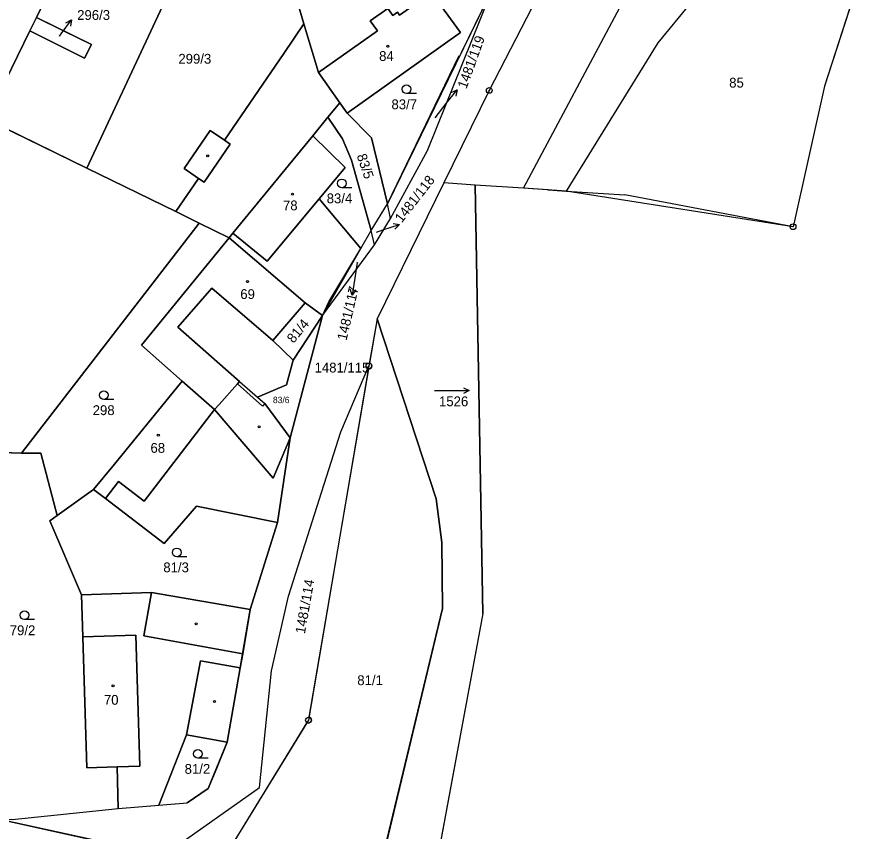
# Model space of a CAD drawing. Extents: x -760642 to -757221, y -1092371 to -1088855.
# Drawn here: x -758933.7 to -758787.7, y -1089822.5 to -1089681.5 of the extents above; entities that cross this region are included whole.
import ezdxf

# ---------------------------------------------------------------- set-up
doc = ezdxf.new("R2010")
doc.units = 0
for name, color, linetype in [('Vrstva 1', 7, 'Continuous'), ('Vrstva 13', 7, 'Continuous'), ('Vrstva 16', 7, 'Continuous'), ('Vrstva 18', 7, 'Continuous'), ('Vrstva 19', 7, 'Continuous'), ('Vrstva 24', 7, 'Continuous'), ('Vrstva 25', 7, 'Continuous'), ('Vrstva 26', 7, 'Continuous'), ('Vrstva 27', 7, 'Continuous'), ('Vrstva 28', 7, 'Continuous'), ('Vrstva 4', 7, 'Continuous')]:
    doc.layers.add(name, color=color, linetype=linetype)

msp = doc.modelspace()

# ---------------------------------------------------------------- linework, layer by layer
at = {"layer": 'Vrstva 1'}
for p, q in [((-758897.45, -1089655.89), (-758921.61, -1089707.71)), ((-758836.23, -1089663.58), (-758851.99, -1089694.25)), ((-758846.04, -1089711.19), (-758823.54, -1089668.77)), ((-758926.27, -1089673.32), (-758930.34, -1089681.62)), ((-758851.17, -1089676.07), (-758869.61, -1089713.9)), ((-758862.67, -1089704.66), (-758851.17, -1089676.07)), ((-758885.64, -1089677.33), (-758884.05, -1089682.7)), ((-758862.01, -1089677.31), (-758856.94, -1089684.25)), ((-758817.26, -1089679.2), (-758822.82, -1089686.02)), ((-758930.34, -1089681.62), (-758931.48, -1089683.95)), ((-758920.83, -1089686.29), (-758930.34, -1089681.62)), ((-758884.05, -1089682.7), (-758887.55, -1089687.84)), ((-758884.05, -1089682.7), (-758881.54, -1089691.15)), ((-758931.48, -1089683.95), (-758938.98, -1089699.23)), ((-758931.48, -1089683.95), (-758921.99, -1089688.64)), ((-758856.94, -1089684.25), (-758876.57, -1089698.16)), ((-758921.99, -1089688.64), (-758920.83, -1089686.29)), ((-758822.82, -1089686.02), (-758838.67, -1089711.68)), ((-758887.55, -1089687.84), (-758897.79, -1089702.88)), ((-758877.84, -1089696.37), (-758881.54, -1089691.15)), ((-758851.99, -1089694.25), (-758859.85, -1089710.27)), ((-758879.9, -1089698.89), (-758877.84, -1089696.37)), ((-758877.84, -1089696.37), (-758876.57, -1089698.16)), ((-758938.98, -1089699.23), (-758921.61, -1089707.71)), ((-758882.53, -1089702.1), (-758879.9, -1089698.89)), ((-758879.9, -1089698.89), (-758877.37, -1089702.61)), ((-758876.57, -1089698.16), (-758872.38, -1089702.46)), ((-758904.75, -1089707.78), (-758900.27, -1089701.19)), ((-758900.27, -1089701.19), (-758897.79, -1089702.88)), ((-758882.53, -1089702.1), (-758876.9, -1089707.61)), ((-758877.37, -1089702.61), (-758875.81, -1089706.3)), ((-758872.38, -1089702.46), (-758869.61, -1089713.9)), ((-758869.09, -1089716.42), (-758862.67, -1089704.66)), ((-758875.81, -1089706.3), (-758872.44, -1089718.5)), ((-758921.61, -1089707.71), (-758906.21, -1089715.23)), ((-758902.28, -1089709.47), (-758904.75, -1089707.78)), ((-758881.43, -1089713.02), (-758876.9, -1089707.61)), ((-758902.28, -1089709.47), (-758906.21, -1089715.23)), ((-758859.85, -1089710.27), (-758871.39, -1089733.79)), ((-758854.44, -1089710.64), (-758859.85, -1089710.27)), ((-758881.43, -1089713.02), (-758874.22, -1089721.62)), ((-758872.44, -1089718.5), (-758869.61, -1089713.9)), ((-758869.09, -1089716.42), (-758869.61, -1089713.9)), ((-758906.21, -1089715.23), (-758902.17, -1089717.2)), ((-758871.85, -1089720.98), (-758869.09, -1089716.42)), ((-758902.17, -1089717.2), (-758932.89, -1089757.04)), ((-758902.17, -1089717.2), (-758896.96, -1089719.75)), ((-758902.41, -1089726.41), (-758896.96, -1089719.75)), ((-758896.96, -1089719.75), (-758883.85, -1089731)), ((-758874.22, -1089721.62), (-758872.44, -1089718.5)), ((-758871.85, -1089720.98), (-758872.44, -1089718.5)), ((-758880.83, -1089733.19), (-758871.85, -1089720.98)), ((-758879.72, -1089730.85), (-758874.22, -1089721.62)), ((-758908.04, -1089733.3), (-758902.41, -1089726.41)), ((-758889.45, -1089737.53), (-758883.85, -1089731)), ((-758883.85, -1089731), (-758880.83, -1089733.19)), ((-758880.83, -1089733.19), (-758879.72, -1089730.85)), ((-758912.16, -1089738.33), (-758908.04, -1089733.3)), ((-758880.83, -1089733.19), (-758886.42, -1089754.39)), ((-758885.92, -1089740.95), (-758880.83, -1089733.19)), ((-758871.39, -1089733.79), (-758872.81, -1089741.94)), ((-758871.39, -1089733.79), (-758861.15, -1089764.91)), ((-758912.16, -1089738.33), (-758905.1, -1089744.55)), ((-758889.45, -1089737.53), (-758885.92, -1089740.95)), ((-758885.92, -1089740.95), (-758887.05, -1089745.23)), ((-758872.81, -1089741.94), (-758883.26, -1089803.24)), ((-758877.68, -1089753.34), (-758872.81, -1089741.94)), ((-758905.1, -1089744.55), (-758905.42, -1089744.94)), ((-758905.1, -1089744.55), (-758899.5, -1089749.48)), ((-758916.84, -1089758.91), (-758905.42, -1089744.94)), ((-758895.56, -1089745.01), (-758898.7, -1089748.58)), ((-758895.56, -1089745.01), (-758891.2, -1089748.87)), ((-758892.11, -1089747.33), (-758887.05, -1089745.23)), ((-758892.11, -1089747.33), (-758890.83, -1089748.45)), ((-758898.7, -1089748.58), (-758899.5, -1089749.48)), ((-758890.83, -1089748.45), (-758891.2, -1089748.87)), ((-758886.42, -1089754.39), (-758890.83, -1089748.45)), ((-758886.71, -1089781.78), (-758877.68, -1089753.34)), ((-758886.42, -1089754.39), (-758888.61, -1089769.01)), ((-758932.89, -1089757.04), (-758946.76, -1089756.58)), ((-758932.89, -1089757.04), (-758929.58, -1089757.04)), ((-758929.58, -1089757.04), (-758926.72, -1089767.81)), ((-758920.43, -1089763.32), (-758916.84, -1089758.91)), ((-758926.72, -1089767.81), (-758920.43, -1089763.32)), ((-758920.43, -1089763.32), (-758918.39, -1089764.88)), ((-758918.39, -1089764.88), (-758908.22, -1089772.65)), ((-758861.15, -1089764.91), (-758860.19, -1089772.49)), ((-758902.61, -1089766.19), (-758908.22, -1089772.65)), ((-758888.61, -1089769.01), (-758902.61, -1089766.19)), ((-758928, -1089768.73), (-758926.72, -1089767.81)), ((-758928, -1089768.73), (-758922.54, -1089781.57)), ((-758888.61, -1089769.01), (-758893.33, -1089784.09)), ((-758860.19, -1089772.49), (-758860.09, -1089783.94)), ((-758910.43, -1089781.16), (-758922.54, -1089781.57)), ((-758910.43, -1089781.16), (-758893.33, -1089784.09)), ((-758922.32, -1089788.8), (-758922.54, -1089781.57)), ((-758889.66, -1089794.72), (-758886.71, -1089781.78)), ((-758893.33, -1089784.09), (-758894.65, -1089791.79)), ((-758860.09, -1089783.94), (-758872.24, -1089834.59)), ((-758921.62, -1089811.49), (-758922.32, -1089788.8)), ((-758894.65, -1089791.79), (-758895.06, -1089794.17)), ((-758895.06, -1089794.17), (-758897.32, -1089807.05)), ((-758891.72, -1089814.9), (-758889.66, -1089794.72)), ((-758883.26, -1089803.24), (-758896.92, -1089825.49)), ((-758904.37, -1089805.81), (-758909.15, -1089817.97)), ((-758904.37, -1089805.81), (-758897.32, -1089807.05)), ((-758897.32, -1089807.05), (-758899.14, -1089811.48)), ((-758916.38, -1089811.33), (-758921.62, -1089811.49)), ((-758916.38, -1089811.33), (-758916.21, -1089818.53)), ((-758899.14, -1089811.48), (-758900.63, -1089815.1)), ((-758908.4, -1089826.64), (-758891.72, -1089814.9)), ((-758900.63, -1089815.1), (-758904.26, -1089817.58)), ((-758909.15, -1089817.97), (-758904.26, -1089817.58)), ((-758934.53, -1089820.44), (-758916.21, -1089818.53)), ((-758916.21, -1089818.53), (-758909.15, -1089817.97)), ((-758937.97, -1089820.13), (-758908.4, -1089826.64))]:
    msp.add_line(p, q, dxfattribs=at)
at = {"layer": 'Vrstva 13'}
for p, q in [((-758787.66, -1089673.88), (-758793.98, -1089693.51)), ((-758793.98, -1089693.51), (-758799.44, -1089717.83)), ((-758846.04, -1089711.19), (-758854.44, -1089710.64)), ((-758853.09, -1089784.76), (-758854.44, -1089710.64)), ((-758841.79, -1089711.47), (-758846.04, -1089711.19)), ((-758841.79, -1089711.47), (-758838.67, -1089711.68)), ((-758838.67, -1089711.68), (-758828.55, -1089712.34)), ((-758799.44, -1089717.83), (-758828.55, -1089712.34)), ((-758853.09, -1089784.76), (-758862.96, -1089838.01))]:
    msp.add_line(p, q, dxfattribs=at)
at = {"layer": 'Vrstva 16'}
for p, q in [((-758926.04, -1089684.47), (-758924.276, -1089682.043)), ((-758926.33, -1089684.86), (-758926.04, -1089684.47)), ((-758859.42, -1089696.51), (-758857.571, -1089694.147)), ((-758861.35, -1089698.98), (-758859.42, -1089696.51)), ((-758871.51, -1089718.77), (-758870.38, -1089718.4)), ((-758870.38, -1089718.4), (-758867.53, -1089717.462)), ((-758874.84, -1089724.04), (-758875.25, -1089726.73)), ((-758875.25, -1089726.73), (-758875.701, -1089729.696))]:
    msp.add_line(p, q, dxfattribs=at)
for points in [[(-758925.268, -1089682.558), (-758924.276, -1089682.043), (-758924.46, -1089683.146)], [(-758858.581, -1089694.627), (-758857.571, -1089694.147), (-758857.794, -1089695.243)], [(-758868.637, -1089717.3), (-758867.53, -1089717.462), (-758868.324, -1089718.25)], [(-758875.056, -1089728.782), (-758875.701, -1089729.696), (-758876.045, -1089728.632)]]:
    msp.add_lwpolyline(points, dxfattribs=at)
at = {"layer": 'Vrstva 24'}
for centre, radius in [((-758851.99, -1089694.25), 0.5), ((-758851.99, -1089694.25), 0.0327), ((-758799.44, -1089717.83), 0.5), ((-758799.44, -1089717.83), 0.0327), ((-758872.81, -1089741.94), 0.5), ((-758872.81, -1089741.94), 0.0327), ((-758883.26, -1089803.24), 0.5), ((-758883.26, -1089803.24), 0.0327)]:
    msp.add_circle(centre, radius, dxfattribs=at)
at = {"layer": 'Vrstva 25'}
for p, q in [((-758864.57, -1089694.8), (-758866.32, -1089694.8)), ((-758875.74, -1089711.08), (-758877.49, -1089711.08)), ((-758861.45, -1089746.21), (-758855.45, -1089746.21)), ((-758916.93, -1089747.74), (-758918.68, -1089747.74)), ((-758904.31, -1089774.95), (-758906.06, -1089774.95)), ((-758930.64, -1089785.84), (-758932.39, -1089785.84)), ((-758900.64, -1089809.83), (-758902.39, -1089809.83))]:
    msp.add_line(p, q, dxfattribs=at)
msp.add_lwpolyline([(-758856.45, -1089745.71), (-758855.45, -1089746.21), (-758856.45, -1089746.71)], dxfattribs=at)
for centre, radius in [((-758869.54, -1089686.61), 0.175), ((-758866.32, -1089694.05), 0.75), ((-758900.7, -1089705.58), 0.175), ((-758877.49, -1089710.33), 0.75), ((-758886.03, -1089712.22), 0.175), ((-758893.83, -1089727.34), 0.175), ((-758918.68, -1089746.99), 0.75), ((-758891.79, -1089752.49), 0.175), ((-758909.24, -1089753.9), 0.175), ((-758906.06, -1089774.2), 0.75), ((-758932.39, -1089785.09), 0.75), ((-758902.7, -1089786.58), 0.175), ((-758917.08, -1089797.31), 0.175), ((-758899.53, -1089800.02), 0.175), ((-758902.39, -1089809.08), 0.75)]:
    msp.add_circle(centre, radius, dxfattribs=at)
at = {"layer": 'Vrstva 26'}
for points in [[(-758916.3, -1089625.5), (-758949.19, -1089694.25), (-758938.98, -1089699.23), (-758931.48, -1089683.95), (-758930.34, -1089681.62), (-758926.27, -1089673.32), (-758913.77, -1089627.67), (-758916.3, -1089625.5)], [(-758925.644, -1089683.926), (-758920.83, -1089686.29), (-758921.99, -1089688.64), (-758931.48, -1089683.95), (-758938.98, -1089699.23), (-758921.61, -1089707.71), (-758897.45, -1089655.89), (-758894.2, -1089649.19), (-758897.14, -1089645.53), (-758899.45, -1089641.9), (-758901.79, -1089638.23), (-758902.79, -1089636.72), (-758904.5, -1089640.06), (-758913.77, -1089627.67), (-758926.27, -1089673.32), (-758930.34, -1089681.62), (-758925.644, -1089683.926)], [(-758887.39, -1089670.98), (-758890.72, -1089658.51), (-758892.71, -1089653.18), (-758894.2, -1089649.19), (-758897.45, -1089655.89), (-758921.61, -1089707.71), (-758906.21, -1089715.23), (-758902.28, -1089709.47), (-758904.75, -1089707.78), (-758900.27, -1089701.19), (-758897.79, -1089702.88), (-758887.55, -1089687.84), (-758884.05, -1089682.7), (-758885.64, -1089677.33), (-758887.39, -1089670.98)], [(-758881.54, -1089691.15), (-758871.34, -1089683.92), (-758872.57, -1089682.19), (-758869.54, -1089680.04), (-758868.66, -1089681.29), (-758867.86, -1089680.72), (-758867.51, -1089681.21), (-758862.01, -1089677.31), (-758860.46, -1089676.21), (-758853.08, -1089674.92), (-758853.39, -1089667.08), (-758877.98, -1089668.72), (-758876.34, -1089674.39), (-758885.64, -1089677.33), (-758884.05, -1089682.7), (-758881.54, -1089691.15)], [(-758876.57, -1089698.16), (-758872.38, -1089702.46), (-758869.61, -1089713.9), (-758851.17, -1089676.07), (-758853.08, -1089674.92), (-758860.46, -1089676.21), (-758862.01, -1089677.31), (-758856.94, -1089684.25), (-758876.57, -1089698.16)], [(-758867.51, -1089681.21), (-758867.86, -1089680.72), (-758868.66, -1089681.29), (-758869.54, -1089680.04), (-758872.57, -1089682.19), (-758871.34, -1089683.92), (-758881.54, -1089691.15), (-758877.84, -1089696.37), (-758876.57, -1089698.16), (-758856.94, -1089684.25), (-758862.01, -1089677.31), (-758867.51, -1089681.21)], [(-758925.644, -1089683.926), (-758930.34, -1089681.62), (-758931.48, -1089683.95), (-758921.99, -1089688.64), (-758920.83, -1089686.29), (-758925.644, -1089683.926)], [(-758896.96, -1089719.75), (-758896.33, -1089718.98), (-758882.53, -1089702.1), (-758879.9, -1089698.89), (-758877.84, -1089696.37), (-758881.54, -1089691.15), (-758884.05, -1089682.7), (-758887.55, -1089687.84), (-758897.79, -1089702.88), (-758896.81, -1089703.55), (-758901.29, -1089710.14), (-758902.28, -1089709.47), (-758906.21, -1089715.23), (-758902.17, -1089717.2), (-758896.96, -1089719.75)], [(-758906.21, -1089715.23), (-758921.61, -1089707.71), (-758938.98, -1089699.23), (-758949.19, -1089694.25), (-758964.56, -1089686.74), (-758974.54, -1089701.27), (-758971.37, -1089702.86), (-758990.85, -1089743.47), (-758977.57, -1089750.63), (-758963.52, -1089755.7), (-758946.76, -1089756.58), (-758932.89, -1089757.04), (-758902.17, -1089717.2), (-758906.21, -1089715.23)], [(-758879.9, -1089698.89), (-758877.37, -1089702.61), (-758875.81, -1089706.3), (-758872.44, -1089718.5), (-758869.61, -1089713.9), (-758872.38, -1089702.46), (-758876.57, -1089698.16), (-758877.84, -1089696.37), (-758879.9, -1089698.89)], [(-758882.53, -1089702.1), (-758876.9, -1089707.61), (-758881.43, -1089713.02), (-758874.22, -1089721.62), (-758872.44, -1089718.5), (-758875.81, -1089706.3), (-758877.37, -1089702.61), (-758879.9, -1089698.89), (-758882.53, -1089702.1)], [(-758902.28, -1089709.47), (-758901.29, -1089710.14), (-758896.81, -1089703.55), (-758897.79, -1089702.88), (-758900.27, -1089701.19), (-758904.75, -1089707.78), (-758902.28, -1089709.47)], [(-758890.44, -1089723.79), (-758881.43, -1089713.02), (-758876.9, -1089707.61), (-758882.53, -1089702.1), (-758896.33, -1089718.98), (-758890.44, -1089723.79)], [(-758881.43, -1089713.02), (-758890.44, -1089723.79), (-758896.33, -1089718.98), (-758896.96, -1089719.75), (-758883.85, -1089731), (-758880.83, -1089733.19), (-758879.72, -1089730.85), (-758874.22, -1089721.62), (-758881.43, -1089713.02)], [(-758902.17, -1089717.2), (-758932.89, -1089757.04), (-758929.58, -1089757.04), (-758926.72, -1089767.81), (-758920.43, -1089763.32), (-758916.84, -1089758.91), (-758905.42, -1089744.94), (-758905.1, -1089744.55), (-758912.16, -1089738.33), (-758908.04, -1089733.3), (-758902.41, -1089726.41), (-758896.96, -1089719.75), (-758902.17, -1089717.2)], [(-758899.5, -1089749.48), (-758898.7, -1089748.58), (-758895.56, -1089745.01), (-758895.2, -1089744.6), (-758905.86, -1089735.22), (-758900, -1089728.48), (-758889.45, -1089737.53), (-758883.85, -1089731), (-758896.96, -1089719.75), (-758902.41, -1089726.41), (-758908.04, -1089733.3), (-758912.16, -1089738.33), (-758905.1, -1089744.55), (-758899.5, -1089749.48)], [(-758889.45, -1089737.53), (-758900, -1089728.48), (-758905.86, -1089735.22), (-758895.2, -1089744.6), (-758892.11, -1089747.33), (-758887.05, -1089745.23), (-758885.92, -1089740.95), (-758889.45, -1089737.53)], [(-758889.45, -1089737.53), (-758885.92, -1089740.95), (-758880.83, -1089733.19), (-758883.85, -1089731), (-758889.45, -1089737.53)], [(-758896.451, -1089825.663), (-758872.24, -1089834.59), (-758860.09, -1089783.94), (-758860.19, -1089772.49), (-758861.15, -1089764.91), (-758871.39, -1089733.79), (-758872.724, -1089741.447)], [(-758896.451, -1089825.663), (-758872.24, -1089834.59), (-758860.09, -1089783.94), (-758860.19, -1089772.49), (-758861.15, -1089764.91), (-758871.39, -1089733.79), (-758872.724, -1089741.447)], [(-758885.92, -1089740.95), (-758887.05, -1089745.23), (-758892.11, -1089747.33), (-758890.83, -1089748.45), (-758886.42, -1089754.39), (-758880.83, -1089733.19), (-758885.92, -1089740.95)], [(-758872.894, -1089742.433), (-758883.176, -1089802.747)], [(-758872.894, -1089742.433), (-758883.176, -1089802.747)], [(-758916.14, -1089761.95), (-758911.7, -1089765.36), (-758899.5, -1089749.48), (-758905.1, -1089744.55), (-758905.42, -1089744.94), (-758916.84, -1089758.91), (-758920.43, -1089763.32), (-758918.39, -1089764.88), (-758916.14, -1089761.95)], [(-758889.4, -1089761.34), (-758886.42, -1089754.39), (-758890.83, -1089748.45), (-758891.2, -1089748.87), (-758895.56, -1089745.01), (-758898.7, -1089748.58), (-758899.5, -1089749.48), (-758889.4, -1089761.34)], [(-758911.7, -1089765.36), (-758916.14, -1089761.95), (-758918.39, -1089764.88), (-758908.22, -1089772.65), (-758902.61, -1089766.19), (-758888.61, -1089769.01), (-758886.42, -1089754.39), (-758889.4, -1089761.34), (-758899.5, -1089749.48), (-758911.7, -1089765.36)], [(-758946.46, -1089758.4), (-758943.42, -1089780.49), (-758937.97, -1089820.13), (-758934.53, -1089820.44), (-758916.21, -1089818.53), (-758916.38, -1089811.33), (-758921.62, -1089811.49), (-758922.32, -1089788.8), (-758922.54, -1089781.57), (-758928, -1089768.73), (-758926.72, -1089767.81), (-758929.58, -1089757.04), (-758932.89, -1089757.04), (-758946.76, -1089756.58), (-758946.46, -1089758.4)], [(-758926.72, -1089767.81), (-758928, -1089768.73), (-758922.54, -1089781.57), (-758910.43, -1089781.16), (-758893.33, -1089784.09), (-758888.61, -1089769.01), (-758902.61, -1089766.19), (-758908.22, -1089772.65), (-758918.39, -1089764.88), (-758920.43, -1089763.32), (-758926.72, -1089767.81)], [(-758922.32, -1089788.8), (-758913.14, -1089788.52), (-758912.44, -1089811.21), (-758916.38, -1089811.33), (-758916.21, -1089818.53), (-758909.15, -1089817.97), (-758904.37, -1089805.81), (-758901.96, -1089792.95), (-758895.06, -1089794.17), (-758894.65, -1089791.79), (-758911.72, -1089788.65), (-758910.43, -1089781.16), (-758922.54, -1089781.57), (-758922.32, -1089788.8)], [(-758910.43, -1089781.16), (-758911.72, -1089788.65), (-758894.65, -1089791.79), (-758893.33, -1089784.09), (-758910.43, -1089781.16)], [(-758916.38, -1089811.33), (-758912.44, -1089811.21), (-758913.14, -1089788.52), (-758922.32, -1089788.8), (-758921.62, -1089811.49), (-758916.38, -1089811.33)], [(-758895.06, -1089794.17), (-758901.96, -1089792.95), (-758904.37, -1089805.81), (-758897.32, -1089807.05), (-758895.06, -1089794.17)], [(-758883.522, -1089803.666), (-758896.658, -1089825.064)], [(-758883.522, -1089803.666), (-758896.658, -1089825.064)], [(-758897.32, -1089807.05), (-758904.37, -1089805.81), (-758909.15, -1089817.97), (-758904.26, -1089817.58), (-758900.63, -1089815.1), (-758899.14, -1089811.48), (-758897.32, -1089807.05)], [(-758977.118, -1089818.836), (-758981.19, -1089818.61), (-758994.11, -1089817.55), (-758994.67, -1089819.64), (-758995.29, -1089821.97), (-758978.87, -1089822.04), (-758940.36, -1089829.46), (-758915.94, -1089831.98), (-758899.04, -1089835.16), (-758894.95, -1089837.25), (-758873.57, -1089841.83), (-758872.87, -1089838.03), (-758894.48, -1089831.19), (-758895.18, -1089829.55), (-758908.4, -1089826.64), (-758937.97, -1089820.13), (-758956.38, -1089819.99), (-758977.118, -1089818.836)]]:
    msp.add_lwpolyline(points, dxfattribs=at)
for centre, start, end in [((-758872.81, -1089741.94), 0, 80.11639), ((-758872.81, -1089741.94), 0, 80.11639), ((-758872.81, -1089741.94), 260.32561, 0), ((-758872.81, -1089741.94), 260.32561, 0), ((-758883.26, -1089803.24), 0, 80.32561), ((-758883.26, -1089803.24), 0, 80.32561), ((-758883.26, -1089803.24), 238.45288, 0), ((-758883.26, -1089803.24), 238.45288, 0)]:
    msp.add_arc(centre, 0.5, start, end, dxfattribs=at)
at = {"layer": 'Vrstva 27'}
msp.add_lwpolyline([(-758908.4, -1089826.64), (-758937.97, -1089820.13), (-758934.53, -1089820.44), (-758916.21, -1089818.53), (-758904.26, -1089817.58), (-758900.63, -1089815.1), (-758897.32, -1089807.05), (-758895.06, -1089794.17), (-758893.33, -1089784.09), (-758888.61, -1089769.01), (-758886.42, -1089754.39), (-758880.83, -1089733.19), (-758874.22, -1089721.62), (-758872.44, -1089718.5), (-758869.61, -1089713.9), (-758857.17, -1089688.23)], dxfattribs=at)
at = {"layer": 'Vrstva 28'}
msp.add_lwpolyline([(-758787.66, -1089673.88), (-758793.98, -1089693.51), (-758799.44, -1089717.83), (-758838.67, -1089711.68), (-758846.04, -1089711.19), (-758854.44, -1089710.64), (-758853.09, -1089784.76), (-758862.96, -1089838.01)], dxfattribs=at)
at = {"layer": 'Vrstva 4'}
for p, q in [((-758872.57, -1089682.19), (-758869.54, -1089680.04)), ((-758871.34, -1089683.92), (-758872.57, -1089682.19)), ((-758881.54, -1089691.15), (-758871.34, -1089683.92)), ((-758896.33, -1089718.98), (-758882.53, -1089702.1)), ((-758896.81, -1089703.55), (-758901.29, -1089710.14)), ((-758897.79, -1089702.88), (-758896.81, -1089703.55)), ((-758901.29, -1089710.14), (-758902.28, -1089709.47)), ((-758890.44, -1089723.79), (-758881.43, -1089713.02)), ((-758896.96, -1089719.75), (-758896.33, -1089718.98)), ((-758896.33, -1089718.98), (-758890.44, -1089723.79)), ((-758900, -1089728.48), (-758905.86, -1089735.22)), ((-758900, -1089728.48), (-758889.45, -1089737.53)), ((-758905.86, -1089735.22), (-758895.2, -1089744.6)), ((-758895.2, -1089744.6), (-758895.56, -1089745.01)), ((-758895.2, -1089744.6), (-758892.11, -1089747.33)), ((-758899.5, -1089749.48), (-758911.7, -1089765.36)), ((-758899.5, -1089749.48), (-758889.4, -1089761.34)), ((-758889.4, -1089761.34), (-758886.42, -1089754.39)), ((-758918.39, -1089764.88), (-758916.14, -1089761.95)), ((-758916.14, -1089761.95), (-758911.7, -1089765.36)), ((-758911.72, -1089788.65), (-758910.43, -1089781.16)), ((-758913.14, -1089788.52), (-758922.32, -1089788.8)), ((-758912.44, -1089811.21), (-758913.14, -1089788.52)), ((-758894.65, -1089791.79), (-758911.72, -1089788.65)), ((-758901.96, -1089792.95), (-758904.37, -1089805.81)), ((-758901.96, -1089792.95), (-758895.06, -1089794.17)), ((-758912.44, -1089811.21), (-758916.38, -1089811.33))]:
    msp.add_line(p, q, dxfattribs=at)

# ---------------------------------------------------------------- texts
at = {"layer": 'Vrstva 16'}
msp.add_text('296/3', height=1.7, dxfattribs=at).set_placement((-758923.28, -1089682.04))
for s, rotation, p in [('1481/119', 70.15536, (-758855.94, -1089694.08)), ('1481/118', 52.05789, (-758867.14, -1089717.27)), ('1481/117', 77.0346, (-758876.685, -1089737.624))]:
    msp.add_text(s, height=1.7, rotation=rotation, dxfattribs=at).set_placement(p)
at = {"layer": 'Vrstva 18'}
for s, height, p in [('296/3', 0.1, (-758926.478, -1089684.86)), ('299/3', 1.7, (-758905.771, -1089689.62)), ('85', 1.7, (-758810.481, -1089693.75)), ('83/7', 1.7, (-758868.91, -1089697.5)), ('1481/119', 0.1, (-758861.52, -1089698.98)), ('83/4', 1.7, (-758880.112, -1089713.78)), ('1481/118', 0.1, (-758871.681, -1089718.77)), ('1481/117', 0.1, (-758875.008, -1089724.04)), ('1481/115', 1.7, (-758882.21, -1089743.07)), ('83/6', 1.1, (-758889.41, -1089748.37)), ('1526', 1.7, (-758860.682, -1089748.91)), ('298', 1.7, (-758920.596, -1089750.44)), ('81/3', 1.7, (-758908.374, -1089777.65)), ('79/2', 1.7, (-758934.94, -1089788.54)), ('81/1', 1.7, (-758874.82, -1089797.18)), ('81/2', 1.7, (-758904.692, -1089812.53))]:
    msp.add_text(s, height=height, dxfattribs=at).set_placement(p)
for s, rotation, p in [('83/5', 288.69732, (-758874.941, -1089705.533)), ('81/4', 50.16222, (-758885.86, -1089738.11)), ('1481/114', 79.97796, (-758883.89, -1089788.38))]:
    msp.add_text(s, height=1.7, rotation=rotation, dxfattribs=at).set_placement(p)
at = {"layer": 'Vrstva 19'}
for s, p in [('84', (-758871.04, -1089689.14)), ('78', (-758887.68, -1089715)), ('69', (-758895.06, -1089730.35)), ('68', (-758910.6, -1089756.97)), ('70', (-758918.654, -1089800.58))]:
    msp.add_text(s, height=1.7, dxfattribs=at).set_placement(p)

doc.saveas('drawing.dxf')
